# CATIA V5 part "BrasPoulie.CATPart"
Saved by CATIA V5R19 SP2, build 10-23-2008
Part number: BrasPoulie
Bounding box of the stored display mesh (mm): x 0 to 10, y -100 to 100, z -10 to 10
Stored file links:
  D:\SCHOOL\FRANCE\BANC_POUTRE_EN_MOUSSE\BrasPoulie.CATPart
  C:\Program Files\Dassault Systemes\B19\intel_a\reffiles\standard\MetricThickPitch.txt
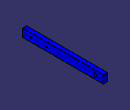
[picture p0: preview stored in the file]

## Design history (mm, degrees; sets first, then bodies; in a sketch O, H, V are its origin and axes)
AxisSystem1: origin (0, 0, 0), X (1, 0, 0), Y (0, 1, 0), Z (0, 0, 1)
Body1 (main body)
  Sketch1 on YZ plane of AxisSystem1, origin (0, 0, 0), H (0, 1, 0), V (0, 0, 1)
    line L1 (100, 10) -> (100, -10)
    line L2 (100, -10) -> (-100, -10)
    line L3 (-100, -10) -> (-100, 10)
    line L4 (-100, 10) -> (100, 10)
    length L4 = 200
    length L1 = 20
    vertical: L1 V, L3 V
    horizontal: L2 H, L4 H
    equidistance: L1 L3 O, L2 L4 O
  Pad1: profile Sketch1, direction (1, 0, 0), length 10
  Sketch2 on start face of Pad1, origin (0, -79.105, -1.3099), H (0, 1, 0), V (0, 0, -1)
    point P1 (-0.895, -1.3099)
    axis line L1 (-70, -1.3099) -> (250, -1.3099)
    reference intersected line E1 through (0, -1.3099) direction (1, 0) from XY plane of AxisSystem1
    reference projected line E2 (-20.895, -21.3099) -> (-20.895, 18.6901) from edge [start face of Pad1 | face of Pad1 from Sketch1.L3]
    distance E2 P1 = 20
    horizontal: L1 H
    coincidence: L1 E1, P1 L1
  Hole1: placed by Sketch2, at (0, -80, 0) direction (1, 0, 0), diameter 4.917, through (limit type 6)
  RectPattern1: of Hole1, direction 1 instances 2, spacing 40, along edge [start face of Pad1 | face of Pad1 from Sketch1.L4] reversed
  Sketch3 on start face of Pad1, origin (0, 83.4264, 0.5842), H (0, 1, 0), V (0, 0, -1)
    point P1 (-3.4264, 0.5842)
    axis line L1 (-197.7326, 0.5842) -> (48.3488, 0.5842)
    reference intersected line E1 through (0, 0.5842) direction (1, 0) from XY plane of AxisSystem1
    reference intersected line E2 through (-83.4264, 0) direction (0, 1) from ZX plane of AxisSystem1
    distance E2 P1 = 80
    horizontal: L1 H
    coincidence: L1 E1, P1 L1
  Hole2: placed by Sketch3, at (0, 80, 0) direction (1, 0, 0), diameter 10, through (limit type 6)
